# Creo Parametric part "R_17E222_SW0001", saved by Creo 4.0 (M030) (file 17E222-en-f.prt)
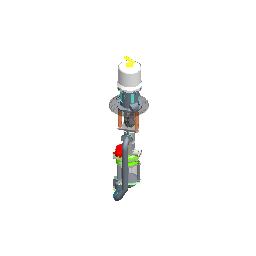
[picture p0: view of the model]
Units: Inch lbm Second (Pro/E Default); INCH, POUND, SECS

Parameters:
  COPY_GEOM_ORIGIN_TYPE = "Part"

Created from: INLBS_PART_SOLID.PRT

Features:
  1. datum plane "RIGHT"
  2. datum plane "TOP"
  3. datum plane "FRONT"
  4. coordinate system
  5. feature "Extern Copy Geom id 40"
  6. feature "Extern Copy Geom id 400"
  7. feature "Extern Copy Geom id 604"
  8. feature "Extern Copy Geom id 692"
  9. feature "Extern Copy Geom id 853"
  10. feature "Extern Copy Geom id 900"
  11. feature "Extern Copy Geom id 947"
  12. feature "Extern Copy Geom id 994"
  13. feature "Extern Copy Geom id 1041"
  14. feature "Extern Copy Geom id 1088"
  15. feature "Extern Copy Geom id 1135"
  16. feature "Extern Copy Geom id 1182"
  17. feature "Extern Copy Geom id 1229"
  18. feature "Extern Copy Geom id 1252"
  19. feature "Extern Copy Geom id 1286"
  20. feature "Extern Copy Geom id 1328"
  21. feature "Extern Copy Geom id 1372"
  22. feature "Extern Copy Geom id 1416"
  23. feature "Extern Copy Geom id 1460"
  24. feature "Extern Copy Geom id 1504"
  25. feature "Extern Copy Geom id 1548"
  26. feature "Extern Copy Geom id 1592"
  27. feature "Extern Copy Geom id 1630"
  28. feature "Extern Copy Geom id 1668"
  29. feature "Extern Copy Geom id 1691"
  30. feature "Extern Copy Geom id 1927"
  31. feature "Extern Copy Geom id 1974"
  32. feature "Extern Copy Geom id 2021"
  33. feature "Extern Copy Geom id 2068"
  34. feature "Extern Copy Geom id 2116"
  35. feature "Extern Copy Geom id 2163"
  36. feature "Extern Copy Geom id 2210"
  37. feature "Extern Copy Geom id 2257"
  38. feature "Extern Copy Geom id 3601"
  39. feature "Extern Copy Geom id 4146"
  40. feature "Extern Copy Geom id 5247"
  41. feature "Extern Copy Geom id 6040"
  42. feature "Extern Copy Geom id 6054"
  43. feature "Extern Copy Geom id 6068"
  44. feature "Extern Copy Geom id 6085"
  45. feature "Extern Copy Geom id 6105"
  46. feature "Extern Copy Geom id 6125"
  47. feature "Extern Copy Geom id 6181"
  48. feature "Extern Copy Geom id 6237"
  49. feature "Extern Copy Geom id 6293"
  50. feature "Extern Copy Geom id 7513"
  51. feature "Extern Copy Geom id 7593"
  52. feature "Extern Copy Geom id 7604"
  53. feature "Extern Copy Geom id 7617"
  54. feature "Extern Copy Geom id 7628"
  55. feature "Extern Copy Geom id 7639"
  56. feature "Extern Copy Geom id 7658"
  57. feature "Extern Copy Geom id 7668"
  58. feature "Extern Copy Geom id 7678"
  59. feature "Extern Copy Geom id 7691"
  60. feature "Extern Copy Geom id 7741"
  61. feature "Extern Copy Geom id 7761"
  62. feature "Extern Copy Geom id 7781"
  63. feature "Extern Copy Geom id 7849"
  64. feature "Extern Copy Geom id 7919"
  65. feature "Extern Copy Geom id 8039"
  66. feature "Extern Copy Geom id 8058"
  67. feature "Extern Copy Geom id 8077"
  68. feature "Extern Copy Geom id 8088"
  69. feature "Extern Copy Geom id 8107"
  70. feature "Extern Copy Geom id 8126"
  71. feature "Extern Copy Geom id 8145"
  72. feature "Extern Copy Geom id 8164"
  73. feature "Extern Copy Geom id 8188"
  74. feature "Extern Copy Geom id 8212"
  75. feature "Extern Copy Geom id 8231"
  76. feature "Extern Copy Geom id 8250"
  77. feature "Extern Copy Geom id 8261"
  78. feature "Extern Copy Geom id 8272"
  79. feature "Extern Copy Geom id 8283"
  80. feature "Extern Copy Geom id 8302"
  81. feature "Extern Copy Geom id 8321"
  82. feature "Extern Copy Geom id 8340"
  83. feature "Extern Copy Geom id 8359"
  84. feature "Extern Copy Geom id 8876"
  85. feature "Extern Copy Geom id 8899"
  86. feature "Extern Copy Geom id 9304"
  87. feature "Extern Copy Geom id 9708"
  88. feature "Extern Copy Geom id 9719"
  89. feature "Extern Copy Geom id 9787"
  90. feature "Extern Copy Geom id 9817"
  91. feature "Extern Copy Geom id 9847"
  92. feature "Extern Copy Geom id 9877"
  93. feature "Extern Copy Geom id 9907"
  94. feature "Extern Copy Geom id 9980"
  95. feature "Extern Copy Geom id 10025"
  96. feature "Extern Copy Geom id 10096"
  97. feature "Extern Copy Geom id 10132"
  98. feature "Extern Copy Geom id 10145"
  99. feature "Extern Copy Geom id 10159"
  100. feature "Extern Copy Geom id 10260"
  101. feature "Extern Copy Geom id 10348"
  102. feature "Extern Copy Geom id 10436"
  103. feature "Extern Copy Geom id 10521"
  104. feature "Extern Copy Geom id 11610"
